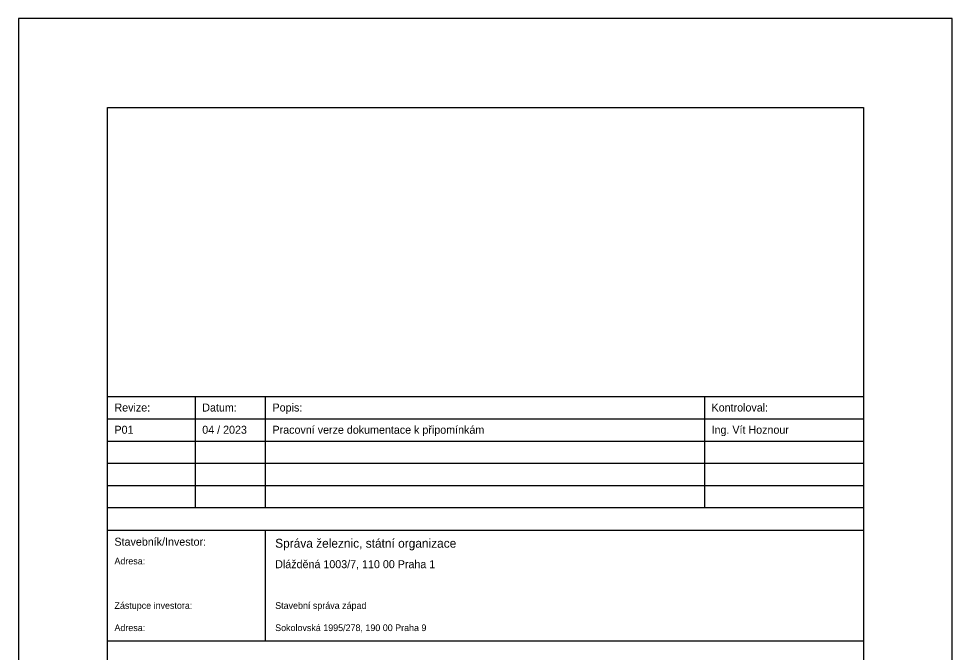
# Model space of a CAD drawing. Extents: x -820819 to -820609, y -1070301 to -1070004.
# Drawn here: x -820819.1 to -820609.1, y -1070146 to -1070003.5 of the extents above; entities that cross this region are included whole.
import ezdxf

# ---------------------------------------------------------------- set-up
doc = ezdxf.new("R2010")
doc.units = 0
doc.layers.add('Popisove_pole', color=7, linetype='Continuous')

msp = doc.modelspace()

# ---------------------------------------------------------------- linework, layer by layer
at = {"layer": 'Popisove_pole'}
for p, q in [((-820779.35, -1070113.52), (-820779.35, -1070088.52)), ((-820763.55, -1070113.52), (-820763.55, -1070088.52)), ((-820664.8, -1070113.52), (-820664.8, -1070088.52)), ((-820799.1, -1070093.52), (-820629.1, -1070093.52)), ((-820799.1, -1070098.52), (-820629.1, -1070098.52)), ((-820799.1, -1070103.52), (-820629.1, -1070103.52)), ((-820799.1, -1070108.52), (-820629.1, -1070108.52)), ((-820763.55, -1070143.52), (-820763.55, -1070118.52))]:
    msp.add_line(p, q, dxfattribs=at)
for points in [[(-820609.1, -1070300.52), (-820609.1, -1070003.52), (-820819.1, -1070003.52), (-820819.1, -1070300.52)], [(-820799.1, -1070023.52), (-820629.1, -1070023.52), (-820629.1, -1070283.52), (-820799.1, -1070283.52)], [(-820799.1, -1070088.52), (-820629.1, -1070088.52), (-820629.1, -1070113.52), (-820799.1, -1070113.52)], [(-820799.1, -1070118.52), (-820629.1, -1070118.52), (-820629.1, -1070143.52), (-820799.1, -1070143.52)]]:
    msp.add_lwpolyline(points, close=True, dxfattribs=at)

# ---------------------------------------------------------------- texts
for s, height, p in [('Revize:', 1.8, (-820797.55, -1070091.87)), ('Datum:', 1.8, (-820777.8, -1070091.87)), ('Popis:', 1.8, (-820762, -1070091.87)), ('Kontroloval:', 1.8, (-820663.25, -1070091.87)), ('P01', 1.8, (-820797.55, -1070096.87)), ('04 / 2023', 1.8, (-820777.8, -1070096.87)), ('Pracovní verze dokumentace k připomínkám', 1.8, (-820762, -1070096.87)), ('Ing. Vít Hoznour', 1.8, (-820663.25, -1070096.87)), ('Stavebník/Investor:', 1.8, (-820797.55, -1070122.05)), ('Správa železnic, státní organizace', 2, (-820761.4, -1070122.5)), ('Adresa:', 1.5, (-820797.55, -1070126.25)), ('Dlážděná 1003/7, 110 00 Praha 1', 1.8, (-820761.4, -1070127.1)), ('Zástupce investora:', 1.5, (-820797.55, -1070136.25)), ('Stavební správa západ', 1.5, (-820761.4, -1070136.25)), ('Adresa:', 1.5, (-820797.55, -1070141.25)), ('Sokolovská 1995/278, 190 00 Praha 9', 1.5, (-820761.4, -1070141.25))]:
    msp.add_text(s, height=height, rotation=360, dxfattribs=at).set_placement(p)

doc.saveas('drawing.dxf')
